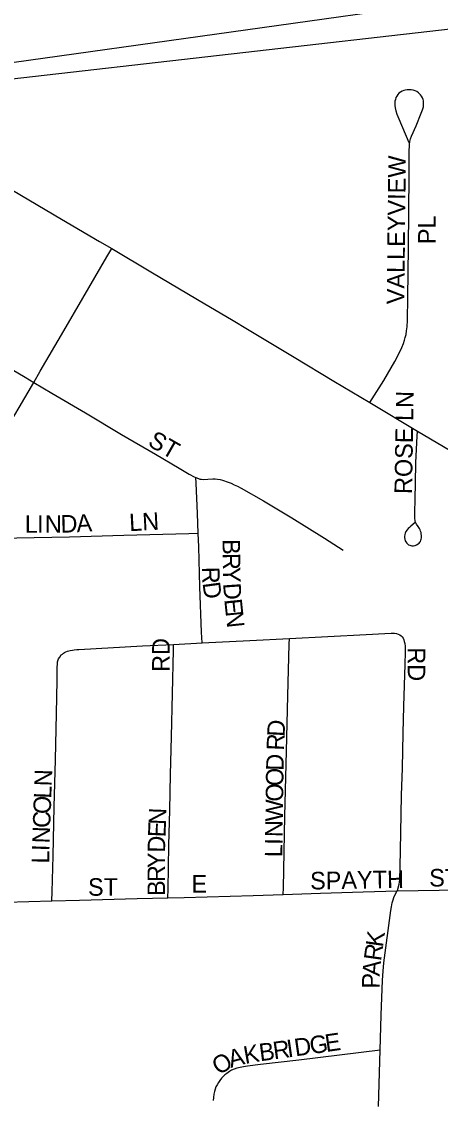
# Model space of a CAD drawing. Extents: x 1772825 to 1773716, y 1138558 to 1139032.
# Drawn here: x 1773364.59 to 1773369.12, y 1138850.34 to 1138861.97 of the extents above; entities that cross this region are included whole.
import ezdxf

# ---------------------------------------------------------------- set-up
doc = ezdxf.new("R2010")
doc.units = 0
for name, color, linetype in [('GM_X_City_Street', 7, 'Continuous'), ('GM_X_City_Street_Text', 7, 'Continuous'), ('SH_Text', 7, 'Continuous')]:
    doc.layers.add(name, color=color, linetype=linetype)

msp = doc.modelspace()

# ---------------------------------------------------------------- linework, layer by layer
at = {"layer": 'GM_X_City_Street'}
for points in [[(1773368.354, 1138857.856), (1773368.404, 1138857.935), (1773368.506, 1138858.096), (1773368.626, 1138858.299), (1773368.68, 1138858.404), (1773368.701, 1138858.452), (1773368.718, 1138858.493), (1773368.729, 1138858.528), (1773368.738, 1138858.558), (1773368.746, 1138858.59), (1773368.752, 1138858.632), (1773368.757, 1138858.675), (1773368.762, 1138858.746), (1773368.767, 1138858.99), (1773368.772, 1138859.531), (1773368.78, 1138860.304), (1773368.781, 1138860.559), (1773368.783, 1138860.641), (1773368.788, 1138860.674), (1773368.795, 1138860.702), (1773368.806, 1138860.731), (1773368.855, 1138860.842), (1773368.911, 1138860.98), (1773368.923, 1138861.013), (1773368.933, 1138861.046), (1773368.935, 1138861.069), (1773368.935, 1138861.092), (1773368.933, 1138861.111), (1773368.93, 1138861.128), (1773368.923, 1138861.146), (1773368.914, 1138861.162), (1773368.904, 1138861.176), (1773368.893, 1138861.189), (1773368.879, 1138861.199), (1773368.861, 1138861.211), (1773368.843, 1138861.22), (1773368.823, 1138861.226), (1773368.801, 1138861.23), (1773368.78, 1138861.231), (1773368.758, 1138861.231), (1773368.738, 1138861.228), (1773368.721, 1138861.223), (1773368.703, 1138861.217), (1773368.685, 1138861.207), (1773368.669, 1138861.193), (1773368.657, 1138861.181), (1773368.646, 1138861.164), (1773368.637, 1138861.148), (1773368.631, 1138861.126), (1773368.627, 1138861.107), (1773368.625, 1138861.083), (1773368.625, 1138861.061), (1773368.63, 1138861.036), (1773368.635, 1138861.005), (1773368.648, 1138860.968), (1773368.668, 1138860.917), (1773368.776, 1138860.661)], [(1773364.139, 1138860.358), (1773365.026, 1138859.834), (1773365.437, 1138859.594), (1773365.568, 1138859.517)], [(1773364.726, 1138858.074), (1773364.797, 1138858.195), (1773365.05, 1138858.629), (1773365.257, 1138858.983), (1773365.517, 1138859.429), (1773365.568, 1138859.517)], [(1773365.568, 1138859.517), (1773366.01, 1138859.257), (1773366.574, 1138858.922), (1773366.86, 1138858.752)], [(1773363.298, 1138858.917), (1773363.663, 1138858.701), (1773364.121, 1138858.429), (1773364.632, 1138858.129), (1773364.726, 1138858.074)], [(1773366.86, 1138858.752), (1773367.052, 1138858.637), (1773367.539, 1138858.347), (1773367.965, 1138858.088), (1773368.354, 1138857.856)], [(1773364.157, 1138856.389), (1773364.156, 1138856.461), (1773364.147, 1138856.775), (1773364.144, 1138856.915), (1773364.146, 1138856.973), (1773364.147, 1138856.999), (1773364.15, 1138857.023), (1773364.155, 1138857.048), (1773364.16, 1138857.073), (1773364.167, 1138857.097), (1773364.175, 1138857.119), (1773364.187, 1138857.147), (1773364.201, 1138857.177), (1773364.242, 1138857.252), (1773364.27, 1138857.304), (1773364.31, 1138857.369), (1773364.402, 1138857.525), (1773364.474, 1138857.646), (1773364.568, 1138857.803), (1773364.726, 1138858.074)], [(1773364.726, 1138858.074), (1773364.922, 1138857.957), (1773365.284, 1138857.745), (1773365.675, 1138857.513), (1773366.041, 1138857.299), (1773366.297, 1138857.148), (1773366.404, 1138857.085), (1773366.46, 1138857.056), (1773366.477, 1138857.047)], [(1773368.354, 1138857.856), (1773368.869, 1138857.548)], [(1773368.845, 1138856.562), (1773368.797, 1138856.521), (1773368.783, 1138856.509), (1773368.769, 1138856.497), (1773368.757, 1138856.484), (1773368.745, 1138856.467), (1773368.736, 1138856.448), (1773368.732, 1138856.432), (1773368.73, 1138856.413), (1773368.731, 1138856.399), (1773368.733, 1138856.382), (1773368.737, 1138856.366), (1773368.744, 1138856.352), (1773368.753, 1138856.341), (1773368.763, 1138856.331), (1773368.774, 1138856.323), (1773368.786, 1138856.316), (1773368.809, 1138856.312), (1773368.828, 1138856.312), (1773368.844, 1138856.314), (1773368.86, 1138856.32), (1773368.878, 1138856.331), (1773368.887, 1138856.34), (1773368.895, 1138856.349), (1773368.902, 1138856.359), (1773368.907, 1138856.37), (1773368.911, 1138856.383), (1773368.912, 1138856.396), (1773368.913, 1138856.409), (1773368.913, 1138856.422), (1773368.911, 1138856.439), (1773368.909, 1138856.455), (1773368.904, 1138856.47), (1773368.898, 1138856.484), (1773368.892, 1138856.496), (1773368.878, 1138856.518), (1773368.86, 1138856.546), (1773368.852, 1138856.56), (1773368.846, 1138856.574), (1773368.843, 1138856.588), (1773368.841, 1138856.602), (1773368.84, 1138856.617), (1773368.84, 1138856.664), (1773368.843, 1138856.82), (1773368.847, 1138856.983), (1773368.853, 1138857.208), (1773368.866, 1138857.493), (1773368.869, 1138857.548)], [(1773368.869, 1138857.548), (1773369.292, 1138857.298), (1773369.592, 1138857.12)], [(1773366.501, 1138856.446), (1773366.495, 1138856.66), (1773366.48, 1138856.986), (1773366.477, 1138857.047)], [(1773366.477, 1138857.047), (1773366.505, 1138857.036), (1773366.52, 1138857.031), (1773366.538, 1138857.029), (1773366.557, 1138857.028), (1773366.606, 1138857.031), (1773366.659, 1138857.034), (1773366.684, 1138857.034), (1773366.712, 1138857.031), (1773366.739, 1138857.025), (1773366.764, 1138857.018), (1773366.825, 1138856.998), (1773366.859, 1138856.985), (1773366.892, 1138856.97), (1773366.927, 1138856.954), (1773366.965, 1138856.934), (1773367.207, 1138856.796), (1773367.514, 1138856.612), (1773367.865, 1138856.395), (1773368.069, 1138856.265)], [(1773364.157, 1138856.389), (1773365.112, 1138856.409), (1773365.699, 1138856.424), (1773366.401, 1138856.443), (1773366.501, 1138856.446)], [(1773366.543, 1138855.263), (1773366.538, 1138855.379), (1773366.519, 1138855.868), (1773366.507, 1138856.301), (1773366.501, 1138856.446)], [(1773367.486, 1138855.31), (1773368.315, 1138855.355), (1773368.517, 1138855.366), (1773368.586, 1138855.37), (1773368.605, 1138855.369), (1773368.623, 1138855.367), (1773368.643, 1138855.364), (1773368.662, 1138855.358), (1773368.678, 1138855.351), (1773368.693, 1138855.341), (1773368.706, 1138855.328), (1773368.715, 1138855.314), (1773368.723, 1138855.297), (1773368.727, 1138855.279), (1773368.732, 1138855.256), (1773368.735, 1138855.229), (1773368.736, 1138855.167), (1773368.733, 1138855.03), (1773368.719, 1138854.582), (1773368.713, 1138854.289), (1773368.703, 1138853.91), (1773368.695, 1138853.621), (1773368.685, 1138853.214), (1773368.679, 1138852.846), (1773368.674, 1138852.707), (1773368.672, 1138852.685), (1773368.667, 1138852.657), (1773368.649, 1138852.587)], [(1773364.923, 1138852.481), (1773364.925, 1138852.576), (1773364.934, 1138852.966), (1773364.947, 1138853.496), (1773364.962, 1138854.003), (1773364.973, 1138854.503), (1773364.978, 1138854.858), (1773364.978, 1138855.006), (1773364.981, 1138855.032), (1773364.983, 1138855.058), (1773364.993, 1138855.09), (1773365.006, 1138855.111), (1773365.023, 1138855.133), (1773365.035, 1138855.143), (1773365.047, 1138855.152), (1773365.059, 1138855.16), (1773365.074, 1138855.167), (1773365.092, 1138855.174), (1773365.118, 1138855.18), (1773365.143, 1138855.185), (1773365.164, 1138855.188), (1773365.192, 1138855.192), (1773365.213, 1138855.193), (1773365.899, 1138855.23), (1773366.236, 1138855.247)], [(1773366.175, 1138852.513), (1773366.176, 1138852.605), (1773366.186, 1138853.08), (1773366.195, 1138853.46), (1773366.204, 1138853.843), (1773366.212, 1138854.249), (1773366.224, 1138854.719), (1773366.234, 1138855.184), (1773366.236, 1138855.247)], [(1773366.236, 1138855.247), (1773366.543, 1138855.263)], [(1773366.543, 1138855.263), (1773367.059, 1138855.288), (1773367.486, 1138855.31)], [(1773367.421, 1138852.549), (1773367.423, 1138852.621), (1773367.438, 1138853.395), (1773367.455, 1138854.094), (1773367.469, 1138854.693), (1773367.484, 1138855.249), (1773367.486, 1138855.31)], [(1773366.175, 1138852.513), (1773366.352, 1138852.518), (1773367.094, 1138852.539), (1773367.421, 1138852.549)], [(1773367.421, 1138852.549), (1773367.822, 1138852.562), (1773368.285, 1138852.578), (1773368.649, 1138852.587)], [(1773368.466, 1138850.869), (1773368.477, 1138851.248), (1773368.491, 1138851.625), (1773368.498, 1138851.722), (1773368.506, 1138851.81), (1773368.582, 1138852.375), (1773368.588, 1138852.416), (1773368.596, 1138852.457), (1773368.606, 1138852.491), (1773368.616, 1138852.516), (1773368.637, 1138852.562), (1773368.649, 1138852.587)], [(1773368.649, 1138852.587), (1773369.103, 1138852.597), (1773369.314, 1138852.601)], [(1773363.504, 1138852.23), (1773363.607, 1138852.28), (1773363.692, 1138852.322), (1773363.76, 1138852.351), (1773363.832, 1138852.379), (1773363.872, 1138852.392), (1773363.916, 1138852.405), (1773363.96, 1138852.416), (1773364.003, 1138852.425), (1773364.115, 1138852.441), (1773364.235, 1138852.456), (1773364.327, 1138852.463), (1773364.426, 1138852.466), (1773364.923, 1138852.481)], [(1773364.923, 1138852.481), (1773365.22, 1138852.487), (1773365.844, 1138852.504), (1773366.175, 1138852.513)], [(1773368.466, 1138850.869), (1773367.587, 1138850.762), (1773367.176, 1138850.714), (1773367.033, 1138850.696), (1773366.992, 1138850.69), (1773366.954, 1138850.682), (1773366.92, 1138850.674), (1773366.891, 1138850.664), (1773366.863, 1138850.652), (1773366.839, 1138850.638), (1773366.811, 1138850.619), (1773366.791, 1138850.604), (1773366.77, 1138850.584), (1773366.755, 1138850.567), (1773366.735, 1138850.543), (1773366.72, 1138850.522), (1773366.705, 1138850.495), (1773366.694, 1138850.472), (1773366.684, 1138850.447), (1773366.677, 1138850.422), (1773366.67, 1138850.394), (1773366.666, 1138850.358), (1773366.662, 1138850.326)], [(1773368.449, 1138850.261), (1773368.466, 1138850.869)]]:
    msp.add_lwpolyline(points, dxfattribs=at)
at = {"layer": 'SH_Text'}
msp.add_lwpolyline([(1773543.413, 1138886.636), (1773358.016, 1138860.614), (1773543.413, 1138881.69)], close=True, dxfattribs=at)

# ---------------------------------------------------------------- texts
at = {"layer": 'GM_X_City_Street_Text'}
for s, height, rotation, p in [('VALLEYVIEW', 0.1894, 89.378, (1773368.727, 1138858.916)), ('PL', 0.1894, 90, (1773369.066, 1138859.566)), ('ROSE LN', 0.1894, 89.0105, (1773368.81, 1138856.868)), ('ST', 0.1894, 330.2568, (1773365.947, 1138857.397)), ('L', 0.189, 0.0546, (1773364.629, 1138856.451)), ('I', 0.189, 0.0437, (1773364.762, 1138856.451)), ('N', 0.189, 0.0379, (1773364.846, 1138856.451)), ('D', 0.189, 1.6498, (1773365.018, 1138856.452)), ('A', 0.189, 3.7722, (1773365.192, 1138856.457)), ('LN', 0.1894, 3.011, (1773365.761, 1138856.468)), ('B', 0.189, 270.7772, (1773366.764, 1138856.382)), ('R', 0.189, 270.7529, (1773366.766, 1138856.232)), ('R', 0.189, 271.3599, (1773366.542, 1138856.082)), ('Y', 0.189, 270.7892, (1773366.768, 1138856.082)), ('D', 0.189, 277.756, (1773366.548, 1138855.909)), ('D', 0.189, 273.9972, (1773366.771, 1138855.904)), ('E', 0.189, 275.9318, (1773366.783, 1138855.731)), ('N', 0.189, 275.9106, (1773366.797, 1138855.599)), ('RD', 0.1894, 90, (1773366.194, 1138854.95)), ('RD', 0.1894, 270, (1773368.765, 1138855.216)), ('D', 0.189, 87.1572, (1773367.434, 1138854.248)), ('R', 0.189, 87.522, (1773367.428, 1138854.099)), ('D', 0.189, 89.0819, (1773367.424, 1138853.883)), ('N', 0.189, 87.9889, (1773364.92, 1138853.714)), ('O', 0.189, 89.1595, (1773367.421, 1138853.717)), ('L', 0.189, 87.978, (1773364.915, 1138853.581)), ('O', 0.189, 89.1595, (1773367.419, 1138853.55)), ('O', 0.189, 87.9889, (1773364.909, 1138853.414)), ('N', 0.189, 87.7041, (1773366.153, 1138853.298)), ('W', 0.189, 89.1594, (1773367.416, 1138853.334)), ('C', 0.189, 87.984, (1773364.904, 1138853.264)), ('N', 0.189, 88.0326, (1773364.898, 1138853.098)), ('E', 0.189, 87.7869, (1773366.148, 1138853.164)), ('N', 0.189, 89.1595, (1773367.413, 1138853.167)), ('D', 0.189, 88.8853, (1773366.144, 1138852.999)), ('I', 0.189, 89.1498, (1773367.412, 1138853.084)), ('L', 0.189, 89.1257, (1773364.893, 1138852.882)), ('I', 0.189, 88.1637, (1773364.895, 1138853.015)), ('Y', 0.189, 89.9688, (1773366.144, 1138852.833)), ('L', 0.189, 89.153, (1773367.41, 1138852.95)), ('R', 0.189, 89.9687, (1773366.144, 1138852.683)), ('SPAYTH', 0.1894, 1.0603, (1773367.712, 1138852.602)), ('ST', 0.1894, 0, (1773368.996, 1138852.635)), ('ST', 0.1894, 0, (1773365.312, 1138852.535)), ('B', 0.189, 89.9757, (1773366.144, 1138852.533)), ('E', 0.189, 0, (1773366.429, 1138852.569)), ('K', 0.189, 81.8853, (1773368.496, 1138851.974)), ('R', 0.189, 82.0073, (1773368.476, 1138851.825)), ('A', 0.189, 84.8788, (1773368.461, 1138851.662)), ('P', 0.189, 89.5082, (1773368.46, 1138851.533)), ('G', 0.189, 8.1578, (1773367.719, 1138850.825)), ('E', 0.189, 8.1633, (1773367.884, 1138850.849)), ('K', 0.189, 10.127, (1773367.009, 1138850.72)), ('B', 0.189, 7.4293, (1773367.171, 1138850.749)), ('R', 0.189, 7.9507, (1773367.322, 1138850.769)), ('I', 0.189, 8.1789, (1773367.471, 1138850.79)), ('D', 0.189, 8.1363, (1773367.553, 1138850.802)), ('O', 0.189, 31.871, (1773366.725, 1138850.595)), ('A', 0.189, 15.2609, (1773366.853, 1138850.677))]:
    msp.add_text(s, height=height, rotation=rotation, dxfattribs=at).set_placement(p)

doc.saveas('drawing.dxf')
